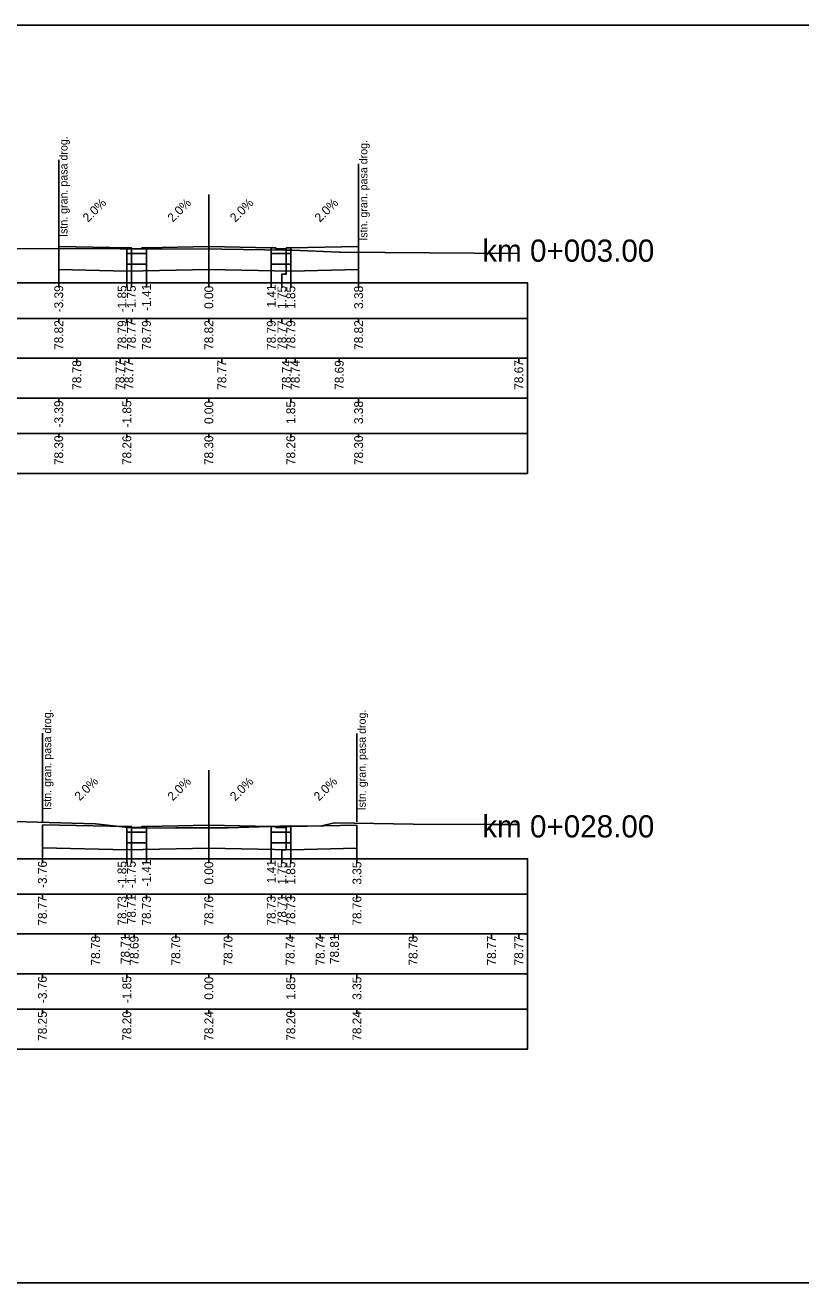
# Model space of a CAD drawing. Extents: x 7492871 to 7493499, y 5802964 to 5802992.
# Drawn here: x 7493437.3 to 7493454.82, y 5802963.88 to 5802992.28 of the extents above; entities that cross this region are included whole.
import ezdxf

# ---------------------------------------------------------------- set-up
doc = ezdxf.new("R2010")
doc.units = 0
for name, color, linetype in [('_wydruk', 7, 'Continuous'), ('opisy_ramki_pop', 7, 'Continuous'), ('pop_comp_kostka', 7, 'Continuous'), ('pop_comp_lawa', 7, 'Continuous'), ('pop_comp_scieralna', 7, 'Continuous'), ('pop_granica_istn', 7, 'Continuous'), ('pop_opis', 7, 'Continuous'), ('pop_os', 7, 'Continuous'), ('pop_pikietaz', 7, 'Continuous'), ('pop_teren', 7, 'Continuous')]:
    doc.layers.add(name, color=color, linetype=linetype)

msp = doc.modelspace()

# ---------------------------------------------------------------- linework, layer by layer
for points in [[(7493438.057, 5802987.283), (7493439.596, 5802987.253), (7493439.696, 5802987.253), (7493439.697, 5802987.233), (7493439.936, 5802987.233), (7493439.937, 5802987.253), (7493440.037, 5802987.253), (7493441.447, 5802987.281), (7493442.857, 5802987.253), (7493442.957, 5802987.253), (7493442.958, 5802987.233), (7493443.197, 5802987.233), (7493443.198, 5802987.253), (7493443.298, 5802987.253), (7493444.83, 5802987.283)], [(7493437.688, 5802974.224), (7493439.596, 5802974.186), (7493439.696, 5802974.186), (7493439.697, 5802974.166), (7493439.936, 5802974.166), (7493439.937, 5802974.186), (7493440.037, 5802974.186), (7493441.447, 5802974.215), (7493442.857, 5802974.186), (7493442.957, 5802974.186), (7493442.958, 5802974.166), (7493443.197, 5802974.166), (7493443.198, 5802974.186), (7493443.298, 5802974.186), (7493444.792, 5802974.216)]]:
    msp.add_lwpolyline(points)
at = {"layer": '_wydruk'}
msp.add_lwpolyline([(7492871.369, 5802992.281), (7493499.283, 5802992.281), (7493499.283, 5802963.881), (7492871.369, 5802963.881)], close=True, dxfattribs=at)
at = {"layer": 'opisy_ramki_pop'}
for points in [[(7493438.057, 5802986.763), (7493438.057, 5802986.659), (7493438.057, 5802986.659), (7493438.057, 5802986.459)], [(7493439.596, 5802986.724), (7493439.596, 5802986.659), (7493439.596, 5802986.659), (7493439.596, 5802986.459)], [(7493441.447, 5802986.761), (7493441.447, 5802986.659), (7493441.447, 5802986.659), (7493441.447, 5802986.459)], [(7493443.298, 5802986.724), (7493443.298, 5802986.659), (7493443.298, 5802986.659), (7493443.298, 5802986.459)], [(7493444.83, 5802986.763), (7493444.83, 5802986.659), (7493444.83, 5802986.659), (7493444.83, 5802986.459)], [(7493437.688, 5802973.704), (7493437.688, 5802973.659), (7493437.688, 5802973.659), (7493437.688, 5802973.459)], [(7493439.596, 5802973.657), (7493439.596, 5802973.659), (7493439.596, 5802973.659), (7493439.596, 5802973.459)], [(7493441.447, 5802973.695), (7493441.447, 5802973.659), (7493441.447, 5802973.659), (7493441.447, 5802973.459)], [(7493443.298, 5802973.657), (7493443.298, 5802973.659), (7493443.298, 5802973.659), (7493443.298, 5802973.459)], [(7493444.792, 5802973.696), (7493444.792, 5802973.659), (7493444.792, 5802973.659), (7493444.792, 5802973.459)]]:
    msp.add_lwpolyline(points, dxfattribs=at)
at = {"layer": 'pop_comp_kostka'}
for p, q in [((7493439.696, 5802987.253), (7493439.596, 5802987.253)), ((7493439.596, 5802987.253), (7493439.596, 5802987.123)), ((7493439.596, 5802987.123), (7493440.037, 5802987.123)), ((7493439.697, 5802987.233), (7493439.696, 5802987.253)), ((7493439.936, 5802987.233), (7493439.697, 5802987.233)), ((7493439.937, 5802987.253), (7493439.936, 5802987.233)), ((7493440.037, 5802987.253), (7493439.937, 5802987.253)), ((7493440.037, 5802987.123), (7493440.037, 5802987.253)), ((7493442.957, 5802987.253), (7493442.857, 5802987.253)), ((7493442.857, 5802987.253), (7493442.857, 5802987.123)), ((7493442.857, 5802987.123), (7493443.298, 5802987.123)), ((7493442.958, 5802987.233), (7493442.957, 5802987.253)), ((7493443.197, 5802987.233), (7493442.958, 5802987.233)), ((7493443.198, 5802987.253), (7493443.197, 5802987.233)), ((7493443.298, 5802987.253), (7493443.198, 5802987.253)), ((7493443.298, 5802987.123), (7493443.298, 5802987.253)), ((7493439.696, 5802974.186), (7493439.596, 5802974.186)), ((7493439.596, 5802974.186), (7493439.596, 5802974.056)), ((7493439.596, 5802974.056), (7493440.037, 5802974.056)), ((7493439.697, 5802974.166), (7493439.696, 5802974.186)), ((7493439.936, 5802974.166), (7493439.697, 5802974.166)), ((7493439.937, 5802974.186), (7493439.936, 5802974.166)), ((7493440.037, 5802974.186), (7493439.937, 5802974.186)), ((7493440.037, 5802974.056), (7493440.037, 5802974.186)), ((7493442.957, 5802974.186), (7493442.857, 5802974.186)), ((7493442.857, 5802974.186), (7493442.857, 5802974.056)), ((7493442.857, 5802974.056), (7493443.298, 5802974.056)), ((7493442.958, 5802974.166), (7493442.957, 5802974.186)), ((7493443.197, 5802974.166), (7493442.958, 5802974.166)), ((7493443.198, 5802974.186), (7493443.197, 5802974.166)), ((7493443.298, 5802974.186), (7493443.198, 5802974.186)), ((7493443.298, 5802974.056), (7493443.298, 5802974.186))]:
    msp.add_line(p, q, dxfattribs=at)
at = {"layer": 'pop_comp_lawa'}
for p, q in [((7493440.037, 5802987.123), (7493439.596, 5802987.123)), ((7493439.596, 5802987.123), (7493439.596, 5802986.882)), ((7493440.037, 5802986.882), (7493440.037, 5802987.123)), ((7493443.298, 5802987.123), (7493442.857, 5802987.123)), ((7493442.857, 5802987.123), (7493442.857, 5802986.882)), ((7493443.298, 5802986.882), (7493443.298, 5802987.123)), ((7493439.596, 5802986.882), (7493440.037, 5802986.882)), ((7493442.857, 5802986.882), (7493443.298, 5802986.882)), ((7493440.037, 5802974.056), (7493439.596, 5802974.056)), ((7493439.596, 5802974.056), (7493439.596, 5802973.816)), ((7493440.037, 5802973.816), (7493440.037, 5802974.056)), ((7493443.298, 5802974.056), (7493442.857, 5802974.056)), ((7493442.857, 5802974.056), (7493442.857, 5802973.816)), ((7493443.298, 5802973.816), (7493443.298, 5802974.056)), ((7493439.596, 5802973.816), (7493440.037, 5802973.816)), ((7493442.857, 5802973.816), (7493443.298, 5802973.816))]:
    msp.add_line(p, q, dxfattribs=at)
at = {"layer": 'pop_comp_scieralna'}
for p, q in [((7493439.596, 5802987.253), (7493438.057, 5802987.283)), ((7493438.057, 5802987.283), (7493438.057, 5802986.763)), ((7493439.596, 5802986.882), (7493439.596, 5802987.253)), ((7493441.447, 5802987.281), (7493440.037, 5802987.253)), ((7493440.037, 5802987.253), (7493440.037, 5802986.882)), ((7493442.857, 5802987.253), (7493441.447, 5802987.281)), ((7493441.447, 5802987.281), (7493441.447, 5802986.761)), ((7493441.447, 5802986.761), (7493441.447, 5802987.281)), ((7493442.857, 5802986.882), (7493442.857, 5802987.253)), ((7493444.83, 5802987.283), (7493443.298, 5802987.253)), ((7493443.298, 5802987.253), (7493443.298, 5802986.882)), ((7493444.83, 5802986.763), (7493444.83, 5802987.283)), ((7493440.037, 5802986.882), (7493439.596, 5802986.882)), ((7493443.298, 5802986.882), (7493442.857, 5802986.882)), ((7493438.057, 5802986.763), (7493439.596, 5802986.724)), ((7493439.596, 5802986.724), (7493441.447, 5802986.761)), ((7493441.447, 5802986.761), (7493443.298, 5802986.724)), ((7493443.298, 5802986.724), (7493444.83, 5802986.763)), ((7493439.596, 5802974.186), (7493437.688, 5802974.224)), ((7493437.688, 5802974.224), (7493437.688, 5802973.704)), ((7493439.596, 5802973.816), (7493439.596, 5802974.186)), ((7493441.447, 5802974.215), (7493440.037, 5802974.186)), ((7493440.037, 5802974.186), (7493440.037, 5802973.816)), ((7493442.857, 5802974.186), (7493441.447, 5802974.215)), ((7493441.447, 5802974.215), (7493441.447, 5802973.695)), ((7493441.447, 5802973.695), (7493441.447, 5802974.215)), ((7493442.857, 5802973.816), (7493442.857, 5802974.186)), ((7493444.792, 5802974.216), (7493443.298, 5802974.186)), ((7493443.298, 5802974.186), (7493443.298, 5802973.816)), ((7493444.792, 5802973.696), (7493444.792, 5802974.216)), ((7493437.688, 5802973.704), (7493439.596, 5802973.657)), ((7493440.037, 5802973.816), (7493439.596, 5802973.816)), ((7493443.298, 5802973.816), (7493442.857, 5802973.816)), ((7493439.596, 5802973.657), (7493441.447, 5802973.695)), ((7493441.447, 5802973.695), (7493443.298, 5802973.657)), ((7493443.298, 5802973.657), (7493444.792, 5802973.696))]:
    msp.add_line(p, q, dxfattribs=at)
at = {"layer": 'pop_granica_istn'}
for p, q in [((7493438.057, 5802987.737), (7493438.057, 5802989.237)), ((7493444.83, 5802987.652), (7493444.83, 5802989.152)), ((7493438.057, 5802987.237), (7493438.057, 5802987.737)), ((7493444.83, 5802987.152), (7493444.83, 5802987.652)), ((7493437.688, 5802974.796), (7493437.688, 5802976.296)), ((7493444.792, 5802974.789), (7493444.792, 5802976.289)), ((7493437.688, 5802974.296), (7493437.688, 5802974.796)), ((7493444.792, 5802974.289), (7493444.792, 5802974.789))]:
    msp.add_line(p, q, dxfattribs=at)
at = {"layer": 'pop_opis'}
for p, q in [((7493438.057, 5802986.359), (7493438.057, 5802986.459)), ((7493439.596, 5802986.359), (7493439.596, 5802986.459)), ((7493439.697, 5802986.359), (7493439.697, 5802986.459)), ((7493440.037, 5802986.359), (7493440.037, 5802986.459)), ((7493441.447, 5802986.359), (7493441.447, 5802986.459)), ((7493442.857, 5802986.359), (7493442.857, 5802986.459)), ((7493443.098, 5802986.359), (7493443.098, 5802986.459)), ((7493443.298, 5802986.359), (7493443.298, 5802986.459)), ((7493444.83, 5802986.359), (7493444.83, 5802986.459)), ((7493434.247, 5802985.659), (7493448.647, 5802985.659)), ((7493434.247, 5802985.659), (7493448.647, 5802985.659)), ((7493434.247, 5802985.659), (7493448.647, 5802985.659)), ((7493434.247, 5802985.659), (7493448.647, 5802985.659)), ((7493438.057, 5802985.559), (7493438.057, 5802985.659)), ((7493439.596, 5802985.559), (7493439.596, 5802985.659)), ((7493439.697, 5802985.559), (7493439.697, 5802985.659)), ((7493440.037, 5802985.559), (7493440.037, 5802985.659)), ((7493441.447, 5802985.559), (7493441.447, 5802985.659)), ((7493442.857, 5802985.559), (7493442.857, 5802985.659)), ((7493443.098, 5802985.559), (7493443.098, 5802985.659)), ((7493443.298, 5802985.559), (7493443.298, 5802985.659)), ((7493444.83, 5802985.559), (7493444.83, 5802985.659)), ((7493438.465, 5802984.659), (7493438.465, 5802984.759)), ((7493439.442, 5802984.659), (7493439.442, 5802984.759)), ((7493439.642, 5802984.659), (7493439.642, 5802984.759)), ((7493441.742, 5802984.659), (7493441.742, 5802984.759)), ((7493443.197, 5802984.659), (7493443.197, 5802984.759)), ((7493443.397, 5802984.659), (7493443.397, 5802984.759)), ((7493444.392, 5802984.659), (7493444.392, 5802984.759)), ((7493448.447, 5802984.659), (7493448.447, 5802984.759)), ((7493438.057, 5802983.759), (7493438.057, 5802983.859)), ((7493439.596, 5802983.759), (7493439.596, 5802983.859)), ((7493441.447, 5802983.759), (7493441.447, 5802983.859)), ((7493443.298, 5802983.759), (7493443.298, 5802983.859)), ((7493444.83, 5802983.759), (7493444.83, 5802983.859)), ((7493434.247, 5802983.059), (7493448.647, 5802983.059)), ((7493438.057, 5802982.959), (7493438.057, 5802983.059)), ((7493439.596, 5802982.959), (7493439.596, 5802983.059)), ((7493441.447, 5802982.959), (7493441.447, 5802983.059)), ((7493443.298, 5802982.959), (7493443.298, 5802983.059)), ((7493444.83, 5802982.959), (7493444.83, 5802983.059)), ((7493437.688, 5802973.359), (7493437.688, 5802973.459)), ((7493439.596, 5802973.359), (7493439.596, 5802973.459)), ((7493439.697, 5802973.359), (7493439.697, 5802973.459)), ((7493440.037, 5802973.359), (7493440.037, 5802973.459)), ((7493441.447, 5802973.359), (7493441.447, 5802973.459)), ((7493442.857, 5802973.359), (7493442.857, 5802973.459)), ((7493443.098, 5802973.359), (7493443.098, 5802973.459)), ((7493443.298, 5802973.359), (7493443.298, 5802973.459)), ((7493444.792, 5802973.359), (7493444.792, 5802973.459)), ((7493434.247, 5802972.659), (7493448.647, 5802972.659)), ((7493434.247, 5802972.659), (7493448.647, 5802972.659)), ((7493434.247, 5802972.659), (7493448.647, 5802972.659)), ((7493434.247, 5802972.659), (7493448.647, 5802972.659)), ((7493437.688, 5802972.559), (7493437.688, 5802972.659)), ((7493439.596, 5802972.559), (7493439.596, 5802972.659)), ((7493439.697, 5802972.559), (7493439.697, 5802972.659)), ((7493440.037, 5802972.559), (7493440.037, 5802972.659)), ((7493441.447, 5802972.559), (7493441.447, 5802972.659)), ((7493442.857, 5802972.559), (7493442.857, 5802972.659)), ((7493443.098, 5802972.559), (7493443.098, 5802972.659)), ((7493443.298, 5802972.559), (7493443.298, 5802972.659)), ((7493444.792, 5802972.559), (7493444.792, 5802972.659)), ((7493438.889, 5802971.659), (7493438.889, 5802971.759)), ((7493439.557, 5802971.659), (7493439.557, 5802971.759)), ((7493439.76, 5802971.659), (7493439.76, 5802971.759)), ((7493440.701, 5802971.659), (7493440.701, 5802971.759)), ((7493441.881, 5802971.659), (7493441.881, 5802971.759)), ((7493443.283, 5802971.659), (7493443.283, 5802971.759)), ((7493443.963, 5802971.659), (7493443.963, 5802971.759)), ((7493444.283, 5802971.659), (7493444.283, 5802971.759)), ((7493446.059, 5802971.659), (7493446.059, 5802971.759)), ((7493447.832, 5802971.659), (7493447.832, 5802971.759)), ((7493448.447, 5802971.659), (7493448.447, 5802971.759)), ((7493437.688, 5802970.759), (7493437.688, 5802970.859)), ((7493439.596, 5802970.759), (7493439.596, 5802970.859)), ((7493441.447, 5802970.759), (7493441.447, 5802970.859)), ((7493443.298, 5802970.759), (7493443.298, 5802970.859)), ((7493444.792, 5802970.759), (7493444.792, 5802970.859)), ((7493434.247, 5802970.059), (7493448.647, 5802970.059)), ((7493437.688, 5802969.959), (7493437.688, 5802970.059)), ((7493439.596, 5802969.959), (7493439.596, 5802970.059)), ((7493441.447, 5802969.959), (7493441.447, 5802970.059)), ((7493443.298, 5802969.959), (7493443.298, 5802970.059)), ((7493444.792, 5802969.959), (7493444.792, 5802970.059))]:
    msp.add_line(p, q, dxfattribs=at)
for points in [[(7493438.057, 5802987.283), (7493438.057, 5802986.659), (7493438.057, 5802986.659), (7493438.057, 5802986.459)], [(7493439.596, 5802987.253), (7493439.596, 5802986.659), (7493439.596, 5802986.659), (7493439.596, 5802986.459)], [(7493439.697, 5802987.233), (7493439.697, 5802986.659), (7493439.697, 5802986.659), (7493439.697, 5802986.459)], [(7493440.037, 5802987.253), (7493440.037, 5802986.659), (7493440.037, 5802986.659), (7493440.037, 5802986.459)], [(7493441.447, 5802987.281), (7493441.447, 5802986.659), (7493441.447, 5802986.659), (7493441.447, 5802986.459)], [(7493442.857, 5802987.253), (7493442.857, 5802986.659), (7493442.857, 5802986.659), (7493442.857, 5802986.459)], [(7493443.197, 5802987.233), (7493443.197, 5802986.659), (7493443.098, 5802986.659), (7493443.098, 5802986.459)], [(7493443.298, 5802987.253), (7493443.298, 5802986.659), (7493443.298, 5802986.659), (7493443.298, 5802986.459)], [(7493444.83, 5802987.283), (7493444.83, 5802986.659), (7493444.83, 5802986.659), (7493444.83, 5802986.459)], [(7493437.688, 5802974.224), (7493437.688, 5802973.659), (7493437.688, 5802973.659), (7493437.688, 5802973.459)], [(7493439.596, 5802974.186), (7493439.596, 5802973.659), (7493439.596, 5802973.659), (7493439.596, 5802973.459)], [(7493439.697, 5802974.166), (7493439.697, 5802973.659), (7493439.697, 5802973.659), (7493439.697, 5802973.459)], [(7493440.037, 5802974.186), (7493440.037, 5802973.659), (7493440.037, 5802973.659), (7493440.037, 5802973.459)], [(7493441.447, 5802974.215), (7493441.447, 5802973.659), (7493441.447, 5802973.659), (7493441.447, 5802973.459)], [(7493442.857, 5802974.186), (7493442.857, 5802973.659), (7493442.857, 5802973.659), (7493442.857, 5802973.459)], [(7493443.197, 5802974.166), (7493443.197, 5802973.659), (7493443.098, 5802973.659), (7493443.098, 5802973.459)], [(7493443.298, 5802974.186), (7493443.298, 5802973.659), (7493443.298, 5802973.659), (7493443.298, 5802973.459)], [(7493444.792, 5802974.216), (7493444.792, 5802973.659), (7493444.792, 5802973.659), (7493444.792, 5802973.459)]]:
    msp.add_lwpolyline(points, dxfattribs=at)
for points in [[(7493434.247, 5802986.459), (7493434.247, 5802984.759), (7493448.647, 5802984.759), (7493448.647, 5802986.459)], [(7493434.247, 5802986.459), (7493434.247, 5802984.759), (7493448.647, 5802984.759), (7493448.647, 5802986.459)], [(7493434.247, 5802986.459), (7493434.247, 5802984.759), (7493448.647, 5802984.759), (7493448.647, 5802986.459)], [(7493434.247, 5802986.459), (7493434.247, 5802984.759), (7493448.647, 5802984.759), (7493448.647, 5802986.459)], [(7493434.247, 5802984.759), (7493434.247, 5802983.859), (7493448.647, 5802983.859), (7493448.647, 5802984.759)], [(7493434.247, 5802983.859), (7493434.247, 5802982.159), (7493448.647, 5802982.159), (7493448.647, 5802983.859)], [(7493434.247, 5802973.459), (7493434.247, 5802971.759), (7493448.647, 5802971.759), (7493448.647, 5802973.459)], [(7493434.247, 5802973.459), (7493434.247, 5802971.759), (7493448.647, 5802971.759), (7493448.647, 5802973.459)], [(7493434.247, 5802973.459), (7493434.247, 5802971.759), (7493448.647, 5802971.759), (7493448.647, 5802973.459)], [(7493434.247, 5802973.459), (7493434.247, 5802971.759), (7493448.647, 5802971.759), (7493448.647, 5802973.459)], [(7493434.247, 5802971.759), (7493434.247, 5802970.859), (7493448.647, 5802970.859), (7493448.647, 5802971.759)], [(7493434.247, 5802970.859), (7493434.247, 5802969.159), (7493448.647, 5802969.159), (7493448.647, 5802970.859)]]:
    msp.add_lwpolyline(points, close=True, dxfattribs=at)
at = {"layer": 'pop_os'}
for p, q in [((7493441.447, 5802988.459), (7493441.447, 5802986.459)), ((7493441.447, 5802975.459), (7493441.447, 5802973.459))]:
    msp.add_line(p, q, dxfattribs=at)
at = {"layer": 'pop_teren'}
for points in [[(7493434.447, 5802987.226), (7493438.465, 5802987.235), (7493439.442, 5802987.232), (7493439.455, 5802987.229), (7493439.578, 5802987.231), (7493441.742, 5802987.225), (7493443.197, 5802987.203), (7493443.332, 5802987.203), (7493444.392, 5802987.151), (7493444.41, 5802987.155), (7493448.447, 5802987.127)], [(7493434.447, 5802974.341), (7493434.543, 5802974.34), (7493435.48, 5802974.346), (7493438.889, 5802974.243), (7493439.557, 5802974.168), (7493439.76, 5802974.147), (7493440.701, 5802974.156), (7493441.881, 5802974.158), (7493443.283, 5802974.2), (7493443.963, 5802974.196), (7493444.283, 5802974.267), (7493446.059, 5802974.241), (7493447.832, 5802974.233), (7493448.447, 5802974.233)]]:
    msp.add_lwpolyline(points, dxfattribs=at)

# ---------------------------------------------------------------- texts
at = {"layer": 'pop_granica_istn'}
for p in [(7493438.255, 5802987.498), (7493445.028, 5802987.413), (7493437.886, 5802974.558), (7493444.991, 5802974.55)]:
    msp.add_text('Istn. gran. pasa drog.', height=0.18, rotation=90, dxfattribs=at).set_placement(p)
at = {"layer": 'pop_opis'}
for s, rotation, p in [('2.0%', 45, (7493438.718, 5802987.818)), ('2.0%', 45, (7493440.633, 5802987.817)), ('2.0%', 45, (7493442.043, 5802987.817)), ('2.0%', 45, (7493443.955, 5802987.818)), ('-3.39', 90, (7493438.157, 5802985.797)), ('-1.85', 90, (7493439.585, 5802985.796)), ('-1.75', 90, (7493439.797, 5802985.796)), ('-1.41', 90, (7493440.137, 5802985.829)), ('0.00', 90, (7493441.547, 5802985.874)), ('1.41', 90, (7493442.957, 5802985.905)), ('1.75', 90, (7493443.198, 5802985.873)), ('1.85', 90, (7493443.398, 5802985.873)), ('3.38', 90, (7493444.93, 5802985.873)), ('78.82', 90, (7493438.157, 5802984.948)), ('78.79', 90, (7493439.585, 5802984.946)), ('78.77', 90, (7493439.797, 5802984.947)), ('78.79', 90, (7493440.137, 5802984.946)), ('78.82', 90, (7493441.547, 5802984.948)), ('78.79', 90, (7493442.957, 5802984.946)), ('78.77', 90, (7493443.198, 5802984.947)), ('78.79', 90, (7493443.398, 5802984.946)), ('78.82', 90, (7493444.93, 5802984.948)), ('78.78', 90, (7493438.565, 5802984.046)), ('78.77', 90, (7493439.542, 5802984.047)), ('78.77', 90, (7493439.742, 5802984.047)), ('78.77', 90, (7493441.842, 5802984.047)), ('78.74', 90, (7493443.297, 5802984.047)), ('78.74', 90, (7493443.497, 5802984.047)), ('78.69', 90, (7493444.492, 5802984.046)), ('78.67', 90, (7493448.547, 5802984.047)), ('-3.39', 90, (7493438.157, 5802983.197)), ('-1.85', 90, (7493439.696, 5802983.196)), ('0.00', 90, (7493441.547, 5802983.274)), ('1.85', 90, (7493443.398, 5802983.273)), ('3.38', 90, (7493444.93, 5802983.273)), ('78.30', 90, (7493438.157, 5802982.347)), ('78.26', 90, (7493439.696, 5802982.347)), ('78.30', 90, (7493441.547, 5802982.347)), ('78.26', 90, (7493443.398, 5802982.347)), ('78.30', 90, (7493444.93, 5802982.347)), ('2.0%', 45, (7493438.533, 5802974.755)), ('2.0%', 45, (7493440.633, 5802974.75)), ('2.0%', 45, (7493442.043, 5802974.75)), ('2.0%', 45, (7493443.936, 5802974.751)), ('-1.41', 90, (7493440.137, 5802972.829)), ('-3.76', 90, (7493437.788, 5802972.798)), ('-1.85', 90, (7493439.585, 5802972.796)), ('-1.75', 90, (7493439.797, 5802972.796)), ('0.00', 90, (7493441.547, 5802972.874)), ('1.41', 90, (7493442.957, 5802972.905)), ('1.75', 90, (7493443.198, 5802972.873)), ('1.85', 90, (7493443.398, 5802972.873)), ('3.35', 90, (7493444.892, 5802972.873)), ('78.77', 90, (7493437.788, 5802971.947)), ('78.73', 90, (7493439.585, 5802971.947)), ('78.71', 90, (7493439.797, 5802971.978)), ('78.73', 90, (7493440.137, 5802971.947)), ('78.76', 90, (7493441.547, 5802971.947)), ('78.73', 90, (7493442.957, 5802971.947)), ('78.71', 90, (7493443.198, 5802971.978)), ('78.73', 90, (7493443.398, 5802971.947)), ('78.76', 90, (7493444.892, 5802971.947)), ('78.71', 90, (7493439.657, 5802971.078)), ('78.81', 90, (7493444.383, 5802971.078)), ('78.78', 90, (7493438.989, 5802971.046)), ('78.69', 90, (7493439.86, 5802971.046)), ('78.70', 90, (7493440.801, 5802971.047)), ('78.70', 90, (7493441.981, 5802971.047)), ('78.74', 90, (7493443.383, 5802971.047)), ('78.74', 90, (7493444.063, 5802971.047)), ('78.78', 90, (7493446.159, 5802971.046)), ('78.77', 90, (7493447.932, 5802971.047)), ('78.77', 90, (7493448.547, 5802971.047)), ('-3.76', 90, (7493437.788, 5802970.198)), ('-1.85', 90, (7493439.696, 5802970.196)), ('0.00', 90, (7493441.547, 5802970.274)), ('1.85', 90, (7493443.398, 5802970.273)), ('3.35', 90, (7493444.892, 5802970.273)), ('78.25', 90, (7493437.788, 5802969.345)), ('78.20', 90, (7493439.696, 5802969.347)), ('78.24', 90, (7493441.547, 5802969.347)), ('78.20', 90, (7493443.398, 5802969.347)), ('78.24', 90, (7493444.892, 5802969.347))]:
    msp.add_text(s, height=0.2, rotation=rotation, dxfattribs=at).set_placement(p)
at = {"layer": 'pop_pikietaz'}
for s, p in [('km 0+003.00', (7493447.623, 5802986.939)), ('km 0+028.00', (7493447.623, 5802973.939))]:
    msp.add_text(s, height=0.5, dxfattribs=at).set_placement(p)

doc.saveas('drawing.dxf')
